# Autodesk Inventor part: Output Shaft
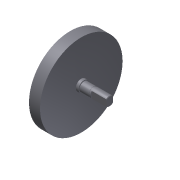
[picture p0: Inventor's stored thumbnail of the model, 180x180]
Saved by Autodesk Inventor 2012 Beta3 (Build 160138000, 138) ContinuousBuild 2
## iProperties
Created: 2011-01
Part Number: Output Shaft
Material: Steel
Document SubType Name: Modeling
Designer: Beta-8540w
Density: 1 g/cm^3
CustomPartVersion: 1
Author: Beta-8540w
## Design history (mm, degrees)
sketch "Main Sketch"
  geometry: L1 (0, 0)-(43, 0) reference; L2 (0, 0)-(0, 45); L3 (12, 45)-(12, 6); L4 (0, 45)-(12, 45); L5 (15, 6)-(15, 5); L6 (12, 6)-(15, 6); L7 (43, 5)-(43, 0); L8 (15, 5)-(43, 5)
  constraints: 16 end point, 5 horizontal, 4 vertical
  dimensions: "d3" = 90 diameter of L4 L1 (derived); "d4" = 12 diameter of L6 L1 (derived); "d5" = 10 diameter of L8 L1 (derived)
revolve "Revolution1" sketch "Main Sketch" stored, may be unused: angle "d6" = 0 deg
chamfer "Chamfer1" distance "d7" = 0.5; stored, may be unused: second distance "d8" = 0.125, angle "d9" = 45 deg
node "Retaining Ring Groove1"
sketch "Sketch3"
  geometry: L1 (-3.571, 3.5)-(3.571, 3.5); L2 (-3.571, -3.5)-(3.571, -3.5); A1 r 5 centre (0, 0) between (-3.571, 3.5) and (3.571, 3.5) reference
  constraints: 4 end point, 4 point on circle, 2 parallel, 1 horizontal
  dimensions: "d10" = 7 distance between parallel lines of L2 L1
extrude "Extrusion1" cut sketch "Sketch3" distance "d11" = 16; taper "d12" = 0 deg
node "Spur Gear Teeth1"
node "Hole2"
body "Solid1"
feature "iFeature27:1"
feature "Spur Gear2"
sketch "Sketch4"
  geometry: 1 further point
hole "Hole1" sketch "Sketch4" diameter "d13" = 3.242; stored, may be unused: countersink angle "d17" = 90 deg, drill point angle "d19" = 120 deg; dims "d14" = 9.49, "d15" = 4, "d16" = 2, "d18" = 11.49
other parameters: "d0" = 0, "d1" = 0, "d2" = 0
